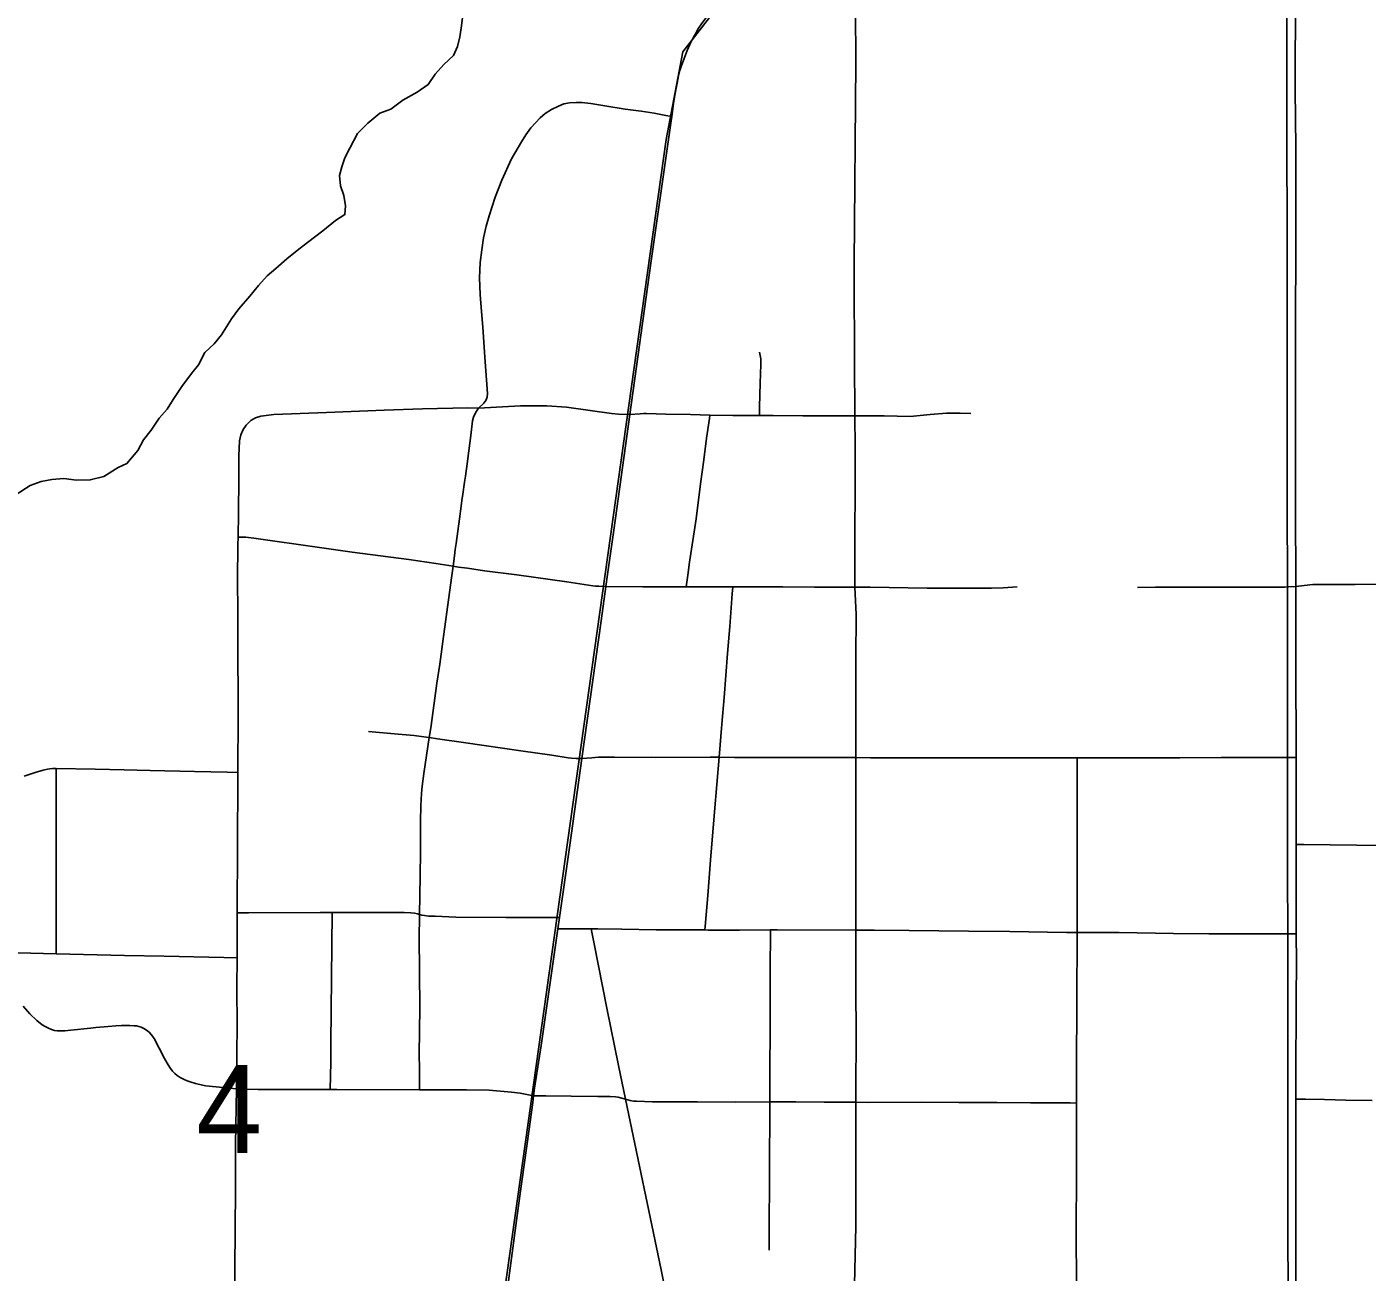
# Model space of a CAD drawing. Extents: x 0 to 34, y 0 to 22.
# Drawn here: x 19.665 to 20.3, y 14.035 to 14.626 of the extents above; entities that cross this region are included whole.
import ezdxf

# ---------------------------------------------------------------- set-up
doc = ezdxf.new("R2010")
doc.units = 0
for name, color, linetype in [('GM_X_City_Street', 7, 'Continuous'), ('GM_X_County_Road', 7, 'Continuous'), ('GM_X_Minor_River', 7, 'Continuous'), ('GM_X_Rail_Line', 7, 'Continuous'), ('GM_X_Section', 7, 'Continuous'), ('GM_X_Section_Text', 7, 'Continuous')]:
    doc.layers.add(name, color=color, linetype=linetype)

msp = doc.modelspace()

# ---------------------------------------------------------------- linework, layer by layer
at = {"layer": 'GM_X_City_Street'}
for points in [[(19.85083, 14.20502), (19.85117, 14.22322), (19.85127, 14.23486), (19.85132, 14.24263), (19.85132, 14.24917), (19.85147, 14.2568), (19.85177, 14.26244), (19.85204, 14.26585), (19.85283, 14.27191), (19.85534, 14.28897), (19.85561, 14.29081), (19.85632, 14.29469), (19.85906, 14.31484), (19.86035, 14.32375), (19.86215, 14.33689), (19.86468, 14.35541), (19.86596, 14.3647), (19.86668, 14.37025), (19.86732, 14.37524), (19.86768, 14.37812), (19.86814, 14.38105), (19.86896, 14.3869), (19.86976, 14.39266), (19.8705, 14.39867), (19.87088, 14.40143), (19.8713, 14.40438), (19.87217, 14.41007), (19.87267, 14.41304), (19.87342, 14.41884), (19.87411, 14.42494), (19.87508, 14.43223), (19.87595, 14.43928), (19.87634, 14.44094), (19.87748, 14.44338), (19.87879, 14.44531), (19.88128, 14.44757), (19.88231, 14.44887), (19.88288, 14.45048), (19.8831, 14.45227), (19.88175, 14.46948), (19.88082, 14.4836), (19.88022, 14.49116), (19.87956, 14.49917), (19.8793, 14.50713), (19.87963, 14.51432), (19.88033, 14.52031), (19.8812, 14.52602), (19.88241, 14.53158), (19.88377, 14.53649), (19.88672, 14.54531), (19.88977, 14.55337), (19.8944, 14.5635), (19.89909, 14.57151), (19.90121, 14.57494), (19.90366, 14.57815), (19.90579, 14.5806), (19.90807, 14.583), (19.91047, 14.58501), (19.91336, 14.58697), (19.91673, 14.58855), (19.91924, 14.58953), (19.92191, 14.59002), (19.92507, 14.59029), (19.92779, 14.59018), (19.93209, 14.5898), (19.93869, 14.58871), (19.94838, 14.58713), (19.9559, 14.58615), (19.96211, 14.58516), (19.96761, 14.58413), (19.97041, 14.5836)], [(20.01203, 14.44173), (20.01213, 14.4459), (20.01237, 14.45703), (20.0127, 14.46602), (20.01276, 14.46737), (20.01267, 14.46868), (20.012, 14.47173)], [(19.95054, 14.44227), (19.95538, 14.44262), (19.95707, 14.44268), (19.95851, 14.44274), (19.96765, 14.44246), (19.97931, 14.44228), (19.98853, 14.44193), (19.99941, 14.44173), (20.01203, 14.44173), (20.01861, 14.44173), (20.03261, 14.44155), (20.03997, 14.44155), (20.04787, 14.44155), (20.05486, 14.44154), (20.05734, 14.44154)], [(19.97732, 14.3605), (19.97803, 14.36606), (19.97882, 14.3722), (19.98195, 14.39279), (19.98411, 14.40934), (19.98561, 14.42071), (19.98696, 14.43102), (19.98829, 14.44026), (19.98853, 14.44193)], [(20.05734, 14.44154), (20.0712, 14.44154), (20.08358, 14.44135), (20.09309, 14.44226), (20.10081, 14.44279), (20.10727, 14.44279), (20.1123, 14.44278)], [(19.76305, 14.00587), (19.76312, 14.03686), (19.76347, 14.07453), (19.76354, 14.09612), (19.7639, 14.12228), (19.76396, 14.12716), (19.76422, 14.15196), (19.7642, 14.17057), (19.76422, 14.18453), (19.76424, 14.19847), (19.76428, 14.20576), (19.76458, 14.26963), (19.76461, 14.27245), (19.76467, 14.2787), (19.7648, 14.29356), (19.76475, 14.30913), (19.76464, 14.32734), (19.76463, 14.3485), (19.76447, 14.36401), (19.76465, 14.38026), (19.76471, 14.38406), (19.76489, 14.39548), (19.76501, 14.41196), (19.76513, 14.42257), (19.76544, 14.4298), (19.76609, 14.43259), (19.76714, 14.43508), (19.76849, 14.43717)], [(19.76471, 14.38406), (19.76585, 14.38405), (19.76845, 14.384), (19.77217, 14.38354), (19.80329, 14.37907), (19.81881, 14.37693), (19.83223, 14.3752), (19.84579, 14.37339), (19.85847, 14.37153), (19.86668, 14.37025), (19.86925, 14.36985), (19.87348, 14.3693), (19.88155, 14.36813), (19.89689, 14.36609), (19.92064, 14.36285), (19.93298, 14.36101), (19.93432, 14.36083), (19.93583, 14.36075), (19.93922, 14.36068)], [(19.93922, 14.36068), (19.95679, 14.3605), (19.97223, 14.36052), (19.97732, 14.3605), (19.9811, 14.36048), (19.99944, 14.36044), (20.00119, 14.36043), (20.02308, 14.36043), (20.03816, 14.36025), (20.05341, 14.36025), (20.05731, 14.36024), (20.06454, 14.36024), (20.09164, 14.35988), (20.10941, 14.35987), (20.1221, 14.35986), (20.12771, 14.36005), (20.13435, 14.36041)], [(19.9862, 14.19768), (19.98633, 14.19926), (19.98754, 14.21411), (19.98889, 14.23074), (19.99079, 14.2537), (19.99296, 14.27967), (19.99422, 14.29526), (19.99524, 14.308), (19.99692, 14.32891), (19.99794, 14.34172), (19.99917, 14.3571), (19.99944, 14.36044)], [(20.19142, 14.36022), (20.19986, 14.36039), (20.20878, 14.36033), (20.24349, 14.36036), (20.25294, 14.3603), (20.26126, 14.36038), (20.26294, 14.36048), (20.26647, 14.36071), (20.27316, 14.36143), (20.2746, 14.36152), (20.27632, 14.36163), (20.29454, 14.36158), (20.32871, 14.36167)], [(19.82662, 14.2919), (19.84063, 14.29055), (19.84821, 14.2899), (19.85284, 14.28931), (19.85534, 14.28897), (19.85938, 14.28841), (19.87161, 14.28667), (19.8815, 14.28518), (19.89888, 14.28263), (19.91363, 14.28054), (19.9213, 14.27939), (19.92292, 14.27926), (19.92502, 14.2791), (19.9278, 14.27903)], [(19.66322, 14.27059), (19.66845, 14.27243), (19.67227, 14.2735), (19.67434, 14.27401), (19.67544, 14.27417), (19.67662, 14.27424), (19.6785, 14.27433)], [(19.67848, 14.18639), (19.67848, 14.21606), (19.67849, 14.23819), (19.67849, 14.25435), (19.6785, 14.26863), (19.6785, 14.27433)], [(19.6785, 14.27433), (19.69696, 14.27395), (19.71064, 14.27365), (19.72297, 14.27337), (19.74405, 14.2729), (19.75948, 14.27256), (19.76461, 14.27245)], [(19.9278, 14.27903), (19.93257, 14.27939), (19.9339, 14.27948), (19.93568, 14.27959), (19.94335, 14.27966), (19.96262, 14.27958), (19.98869, 14.27974), (19.99296, 14.27967), (20.0002, 14.27956), (20.01187, 14.27956), (20.03032, 14.27956), (20.05097, 14.27955), (20.05778, 14.27946), (20.06468, 14.27938), (20.08869, 14.27933), (20.11018, 14.27935), (20.14729, 14.27943), (20.16275, 14.27933), (20.16582, 14.27933), (20.19229, 14.27935), (20.21141, 14.27935), (20.23111, 14.27944), (20.24712, 14.27951), (20.26167, 14.27951), (20.26661, 14.27951)], [(20.16242, 14.02826), (20.16234, 14.0554), (20.1625, 14.08164), (20.16246, 14.1156), (20.16247, 14.13277), (20.1626, 14.16336), (20.16272, 14.19643), (20.16277, 14.20508), (20.16268, 14.25655), (20.16273, 14.27492), (20.16275, 14.27933)], [(20.26657, 14.23829), (20.27025, 14.23824), (20.29531, 14.2379), (20.30764, 14.23783)], [(19.76428, 14.20576), (19.76966, 14.20578), (19.80363, 14.20591), (19.80934, 14.20592), (19.83451, 14.20603), (19.84346, 14.20593), (19.84664, 14.2058), (19.84837, 14.20563), (19.84981, 14.20528), (19.85083, 14.20502), (19.85194, 14.20474), (19.85319, 14.20449), (19.855, 14.20431), (19.85814, 14.20423), (19.86801, 14.20384), (19.89179, 14.20358), (19.9098, 14.20363), (19.9172, 14.20364)], [(19.80842, 14.12201), (19.80868, 14.1349), (19.80876, 14.1408), (19.80865, 14.14385), (19.80934, 14.20592)], [(19.85082, 14.12193), (19.85079, 14.12531), (19.85073, 14.13184), (19.85068, 14.13883), (19.85092, 14.16068), (19.85068, 14.19462), (19.85081, 14.20353), (19.85083, 14.20502)], [(19.91642, 14.19818), (19.9247, 14.19818), (19.93224, 14.19817), (19.93536, 14.19817), (19.9467, 14.198), (19.96311, 14.19783), (19.97615, 14.19783), (19.9862, 14.19768), (19.98766, 14.19765), (20.00254, 14.19765), (20.01731, 14.19778), (20.02048, 14.19782), (20.05779, 14.19765), (20.06652, 14.19764), (20.08311, 14.19746), (20.1112, 14.19712), (20.13083, 14.19695), (20.15774, 14.19643), (20.16272, 14.19643), (20.18262, 14.19642), (20.20852, 14.19608), (20.22527, 14.19591), (20.24947, 14.1959), (20.26132, 14.1959), (20.26666, 14.1959)], [(19.97236, 14.0017), (19.97146, 14.00633), (19.96541, 14.03648), (19.94857, 14.11743), (19.94525, 14.13332), (19.93969, 14.16066), (19.93364, 14.19113), (19.93224, 14.19817)], [(20.01659, 14.04577), (20.01677, 14.09036), (20.01689, 14.10777), (20.01692, 14.11611), (20.01699, 14.12679), (20.01714, 14.15504), (20.01714, 14.18335), (20.01725, 14.1922), (20.01731, 14.19778)], [(19.64402, 14.18721), (19.66037, 14.18682), (19.67848, 14.18639), (19.71088, 14.18562), (19.72974, 14.18523), (19.75804, 14.18465), (19.76422, 14.18453)], [(19.7639, 14.12228), (19.75744, 14.12295), (19.74943, 14.12378), (19.74789, 14.12402), (19.74449, 14.12485), (19.74248, 14.12552), (19.74065, 14.12616), (19.73911, 14.12676), (19.73729, 14.12767), (19.73586, 14.12863), (19.73477, 14.12958), (19.73367, 14.13074), (19.73239, 14.13238), (19.73106, 14.13453), (19.72919, 14.13778), (19.72834, 14.1395), (19.72734, 14.14154), (19.72579, 14.1447), (19.72529, 14.14569), (19.72416, 14.1473), (19.72348, 14.14817), (19.72248, 14.14921), (19.72128, 14.15017), (19.72005, 14.15088), (19.71875, 14.15152), (19.71769, 14.15188), (19.71655, 14.15216), (19.71551, 14.15228), (19.71331, 14.15236), (19.71127, 14.15232), (19.70938, 14.15231), (19.7068, 14.15217), (19.70318, 14.15188), (19.69732, 14.15136), (19.69479, 14.15109), (19.68542, 14.15009), (19.68249, 14.14977), (19.68017, 14.14978), (19.67886, 14.14983), (19.67765, 14.15003), (19.67616, 14.15051), (19.67477, 14.15104), (19.67328, 14.1519), (19.67179, 14.15275), (19.66923, 14.15467), (19.66599, 14.15791), (19.66279, 14.16148)], [(19.7639, 14.12228), (19.76823, 14.12217), (19.77425, 14.12201), (19.80842, 14.12201), (19.81159, 14.12201), (19.85082, 14.12193), (19.8731, 14.12189), (19.88385, 14.12177), (19.89441, 14.12081), (19.89857, 14.12024), (19.90492, 14.11904)], [(19.90492, 14.11904), (19.9107, 14.11899), (19.92267, 14.1189), (19.93537, 14.11873), (19.94119, 14.11863), (19.94376, 14.1185), (19.94499, 14.11834), (19.94617, 14.11806), (19.94857, 14.11743), (19.95078, 14.11685), (19.95223, 14.11654), (19.95379, 14.11642), (19.96127, 14.1162), (19.98264, 14.11612), (20.00049, 14.11605), (20.01692, 14.11611), (20.02932, 14.11614), (20.04273, 14.11602), (20.05072, 14.11594), (20.05773, 14.11594), (20.06394, 14.11584), (20.0893, 14.11593), (20.10667, 14.11583), (20.12472, 14.11583), (20.14061, 14.11573), (20.15945, 14.11562), (20.16246, 14.1156)], [(20.26649, 14.11745), (20.27104, 14.11737), (20.2801, 14.1172), (20.29013, 14.11702), (20.3027, 14.11679)]]:
    msp.add_lwpolyline(points, dxfattribs=at)
at = {"layer": 'GM_X_County_Road'}
msp.add_line((19.91642, 14.19818), (19.9172, 14.20364), dxfattribs=at)
for points in [[(19.97041, 14.5836), (19.97125, 14.58969), (19.97227, 14.59548), (19.97299, 14.59934), (19.97369, 14.6029), (19.97428, 14.6054), (19.97487, 14.60738), (19.97625, 14.61119), (19.97778, 14.61488), (19.97903, 14.61772), (19.98071, 14.6212), (19.9821, 14.62366), (19.98288, 14.62501), (19.98456, 14.62752), (19.9869, 14.6307), (19.98925, 14.63338), (19.99176, 14.63614), (19.99293, 14.63722)], [(20.05734, 14.44154), (20.0572, 14.46813), (20.05701, 14.50643), (20.05697, 14.51391), (20.05777, 14.60907), (20.05767, 14.63462)], [(20.26647, 14.36071), (20.26644, 14.37052), (20.26638, 14.3891), (20.26637, 14.43258), (20.26636, 14.46868), (20.26638, 14.49702), (20.2664, 14.51009), (20.26652, 14.51926), (20.2664, 14.53167), (20.26641, 14.5532), (20.26642, 14.56888), (20.26622, 14.59618), (20.26621, 14.60594), (20.26634, 14.63353)], [(19.95054, 14.44227), (19.96054, 14.51407), (19.96997, 14.58044), (19.97041, 14.5836)], [(19.87879, 14.44531), (19.89875, 14.4463), (19.9112, 14.44628), (19.92047, 14.44565), (19.9419, 14.44266), (19.94511, 14.44239), (19.95054, 14.44227)], [(19.76849, 14.43717), (19.77071, 14.43935), (19.77302, 14.44061), (19.77559, 14.44138), (19.78173, 14.44221), (19.80662, 14.44321), (19.83397, 14.44425), (19.85217, 14.44492), (19.87378, 14.44539), (19.87879, 14.44531)], [(19.93922, 14.36068), (19.93996, 14.36631), (19.94289, 14.38736), (19.95054, 14.44227)], [(20.05731, 14.36024), (20.05733, 14.36531), (20.05741, 14.42675), (20.05734, 14.44154)], [(19.9278, 14.27903), (19.9369, 14.34436), (19.93922, 14.36068)], [(20.05778, 14.27946), (20.05775, 14.28026), (20.05778, 14.32653), (20.05792, 14.34742), (20.05731, 14.36024)], [(20.26661, 14.27951), (20.26662, 14.29018), (20.26651, 14.31456), (20.26647, 14.36071)], [(19.9172, 14.20364), (19.92209, 14.238), (19.9278, 14.27903)], [(20.05779, 14.19765), (20.05777, 14.2039), (20.05777, 14.216), (20.05778, 14.27946)], [(20.26657, 14.23829), (20.26658, 14.24811), (20.2666, 14.27404), (20.26661, 14.27951)], [(20.26666, 14.1959), (20.26656, 14.23128), (20.26657, 14.23829)], [(19.90492, 14.11904), (19.9054, 14.12272), (19.90856, 14.14294), (19.91642, 14.19818)], [(20.05773, 14.11594), (20.05776, 14.1293), (20.05787, 14.14001), (20.05778, 14.17809), (20.05779, 14.19765)], [(20.26649, 14.11745), (20.2665, 14.12414), (20.2665, 14.13928), (20.26656, 14.15215), (20.26662, 14.16512), (20.26671, 14.18237), (20.26666, 14.1959)], [(19.88813, 13.9979), (19.89005, 14.00865), (19.89675, 14.0599), (19.89839, 14.07157), (19.90269, 14.10216), (19.9045, 14.11591), (19.90492, 14.11904)], [(20.05685, 14.00627), (20.05677, 14.00853), (20.05678, 14.01137), (20.05678, 14.01582), (20.05772, 14.05699), (20.05769, 14.08956), (20.05772, 14.10705), (20.05773, 14.11499), (20.05773, 14.11594)], [(20.26645, 14.01718), (20.26645, 14.02263), (20.26647, 14.04679), (20.26648, 14.09373), (20.26649, 14.11745)]]:
    msp.add_lwpolyline(points, dxfattribs=at)
at = {"layer": 'GM_X_Minor_River'}
for points in [[(19.72355, 14.43476), (19.72728, 14.44051), (19.73103, 14.44474), (19.73401, 14.44934), (19.73811, 14.45547), (19.7426, 14.46161), (19.74597, 14.46583), (19.74893, 14.47157), (19.75344, 14.4758), (19.75681, 14.48003), (19.76166, 14.48769), (19.76502, 14.49229), (19.77027, 14.49844), (19.77438, 14.50343), (19.77851, 14.50805), (19.78265, 14.51152), (19.78791, 14.51615), (19.79281, 14.52001), (19.7977, 14.52387), (19.80486, 14.52929), (19.81088, 14.53431), (19.81541, 14.53703), (19.81573, 14.54121), (19.81491, 14.54613), (19.81333, 14.55067), (19.81288, 14.55561), (19.81397, 14.5598), (19.81544, 14.564), (19.81766, 14.56858), (19.82137, 14.57547), (19.82625, 14.58047), (19.8319, 14.58511), (19.8372, 14.58708), (19.84285, 14.59133), (19.84964, 14.59522), (19.85492, 14.59871), (19.85828, 14.60369), (19.8624, 14.6083), (19.86692, 14.61254), (19.86876, 14.61674), (19.86984, 14.62132), (19.87055, 14.62551), (19.87124, 14.63045)], [(19.65891, 14.40389), (19.66608, 14.40855), (19.67138, 14.41052), (19.67631, 14.41134), (19.68201, 14.4118), (19.6881, 14.41112), (19.69457, 14.41121), (19.70101, 14.41281), (19.70781, 14.41708), (19.71196, 14.41903), (19.71721, 14.42518), (19.71981, 14.43015), (19.72355, 14.43476)]]:
    msp.add_lwpolyline(points, dxfattribs=at)
at = {"layer": 'GM_X_Rail_Line'}
msp.add_lwpolyline([(20.49604, 15.97752), (20.47717, 15.90327), (20.38571, 15.64375), (20.2059, 15.099), (20.0763, 14.72575), (20.05407, 14.68967), (20.0154, 14.65678), (19.99496, 14.6392), (19.97576, 14.61421), (19.96774, 14.5727), (19.88713, 13.998), (19.97589, 13.55203)], dxfattribs=at)
at = {"layer": 'GM_X_Section'}
for points in [[(19.25999, 14.63809), (20.26215, 14.63524), (20.2632, 13.61532), (19.25652, 13.61624)], [(21.26087, 14.6354), (21.26959, 14.63583), (21.2938, 13.61037), (20.2632, 13.61532), (20.26215, 14.63524)]]:
    msp.add_lwpolyline(points, close=True, dxfattribs=at)

# ---------------------------------------------------------------- texts
at = {"layer": 'GM_X_Section_Text'}
msp.add_text('4', height=0.04186, rotation=0.00001, dxfattribs=at).set_placement((19.74498, 14.09181))

doc.saveas('drawing.dxf')
